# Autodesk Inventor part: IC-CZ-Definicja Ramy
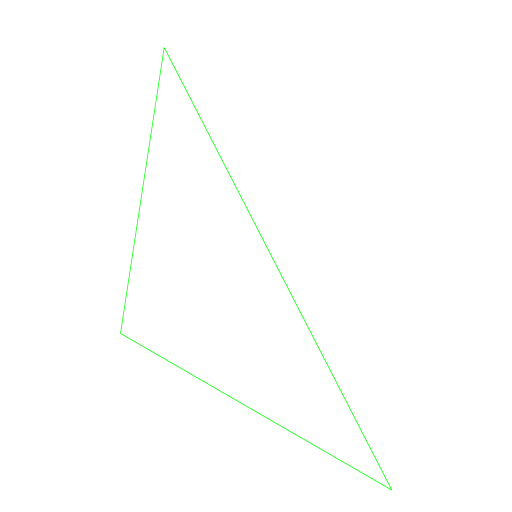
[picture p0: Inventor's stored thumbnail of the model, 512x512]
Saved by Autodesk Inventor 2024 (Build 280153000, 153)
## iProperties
Company: ATC
Created: 2023-03
Part Number: IC-CZ-Definicja Ramy
Document SubType Name: Modeling
Designer: Andrzej Jaskulski
Density: 1 g/cm^3
Material: Kurs-AJ
Appearance: Kurs-AJ
Checked By: A.J.
Engr Approved By: Andrzej Jaskulski
Mfg Approved By: Andrzej Jaskulski
Authority: A.J.
Author: Andrzej Jaskulski
Revision Number: 1/24
Title: A.J.: Kurs R2024-MEP
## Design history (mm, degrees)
sketch "Szkielet Bazowy"
  geometry: L1 (-421.377, -505.696)-(78.628, -505.696); L2 (-421.377, -505.696)-(-1.934, -9.135); L3 (-1.934, -9.135)-(78.628, -505.696)
  constraints: 6 end point, 1 other
node "Bryła2"
